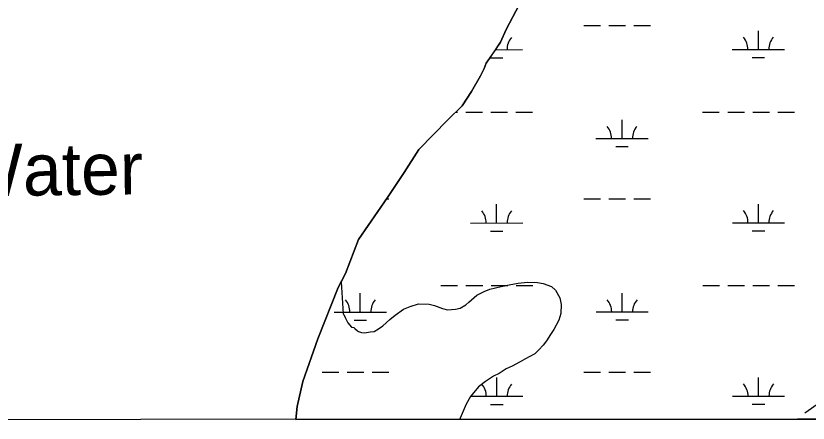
# Model space of a CAD drawing. Extents: x 3279314 to 3317160, y 734079 to 759431.
# Drawn here: x 3297071 to 3298590, y 739456 to 740238 of the extents above; entities that cross this region are included whole.
import ezdxf

# ---------------------------------------------------------------- set-up
doc = ezdxf.new("R2010")
doc.units = 0
for name, color, linetype in [('V-GRID-FRAM', 7, 'Continuous'), ('V-RIVR-IDEN', 7, 'Continuous'), ('V-ROAD-CNTR', 7, 'Continuous'), ('V-SITE-VEGE', 7, 'Continuous'), ('V-TOPO-SHOR', 7, 'Continuous'), ('V-WETL-SWMP', 7, 'Continuous')]:
    doc.layers.add(name, color=color, linetype=linetype)

msp = doc.modelspace()

# ---------------------------------------------------------------- linework, layer by layer
at = {"layer": 'V-GRID-FRAM'}
msp.add_lwpolyline([(3283455.7, 757641.4), (3314923.7, 757657.4), (3314940.9, 739471.9), (3283457, 739455.9), (3283455.7, 757641.4)], dxfattribs=at)
at = {"layer": 'V-ROAD-CNTR'}
msp.add_lwpolyline([(3298583.5, 739475.9), (3298613.5, 739496.6), (3298666.5, 739531.7)], dxfattribs=at)
at = {"layer": 'V-SITE-VEGE'}
for p, q in [((3298035.6, 740258.6), (3298011, 740211.1)), ((3298011, 740211.1), (3298000.3, 740187.3)), ((3298000.3, 740187.3), (3297972.4, 740146.6)), ((3297972.4, 740146.6), (3297968.8, 740136.4)), ((3297968.8, 740136.4), (3297961.7, 740122.8)), ((3297961.7, 740122.8), (3297944.2, 740092.3)), ((3297944.2, 740092.3), (3297926.7, 740065.2)), ((3297926.7, 740065.2), (3297898.9, 740038.2)), ((3297898.9, 740038.2), (3297843.3, 739980.9)), ((3297843.3, 739980.9), (3297815.2, 739936.8)), ((3297815.2, 739936.8), (3297783.7, 739889.3)), ((3297783.7, 739889.3), (3297727.8, 739808.1)), ((3297727.8, 739808.1), (3297702.9, 739743.4)), ((3297702.9, 739743.4), (3297694.4, 739727.1)), ((3297694.4, 739727.1), (3297698.2, 739666)), ((3297979.8, 739713), (3298001.4, 739718.2)), ((3298001.4, 739718.2), (3298016.6, 739721.2)), ((3298016.6, 739721.2), (3298034.2, 739724.9)), ((3298034.2, 739724.9), (3298051.7, 739726.3)), ((3298051.7, 739726.3), (3298070.9, 739726)), ((3298070.9, 739726), (3298082, 739724.2)), ((3298082, 739724.2), (3298097.9, 739718.4)), ((3298097.9, 739718.4), (3298105.8, 739711.1)), ((3297939.5, 739688), (3297954.8, 739701.4)), ((3297954.8, 739701.4), (3297968.5, 739708.3)), ((3297968.5, 739708.3), (3297979.8, 739713)), ((3298105.8, 739711.1), (3298113.5, 739696.6)), ((3297826.9, 739680.1), (3297842.9, 739684.7)), ((3297842.9, 739684.7), (3297863.6, 739684.3)), ((3297863.6, 739684.3), (3297873.2, 739681.8)), ((3297922.6, 739676.3), (3297933.8, 739683.3)), ((3297933.8, 739683.3), (3297939.5, 739688)), ((3298113.5, 739696.6), (3298116.5, 739683.8)), ((3298116.5, 739683.8), (3298115.5, 739666.3)), ((3297797.9, 739663), (3297814, 739674.7)), ((3297814, 739674.7), (3297826.9, 739680.1)), ((3297873.2, 739681.8), (3297889.1, 739676)), ((3297889.1, 739676), (3297898.6, 739673.5)), ((3297898.6, 739673.5), (3297913.8, 739674.8)), ((3297913.8, 739674.8), (3297922.6, 739676.3)), ((3297698.2, 739666), (3297699.8, 739664.4)), ((3297699.8, 739664.4), (3297702.1, 739658.8)), ((3297702.1, 739658.8), (3297707.5, 739648.4)), ((3297774.5, 739642.6), (3297788.2, 739655.1)), ((3297788.2, 739655.1), (3297797.9, 739663)), ((3298112.1, 739653.6), (3298102.3, 739635.4)), ((3298115.5, 739666.3), (3298112.1, 739653.6)), ((3297707.5, 739648.4), (3297714.6, 739640.3)), ((3297714.6, 739640.3), (3297718.6, 739639.4)), ((3297718.6, 739639.4), (3297721, 739637.8)), ((3297721, 739637.8), (3297725.7, 739632.9)), ((3297757.6, 739631.7), (3297766.4, 739637.1)), ((3297766.4, 739637.1), (3297774.5, 739642.6)), ((3297725.7, 739632.9), (3297728.1, 739632.1)), ((3297728.1, 739632.1), (3297733.6, 739629.6)), ((3297733.6, 739629.6), (3297740, 739629.5)), ((3297740, 739629.5), (3297750.4, 739631)), ((3297750.4, 739631), (3297757.6, 739631.7)), ((3298095.7, 739625.9), (3298088.4, 739614)), ((3298102.3, 739635.4), (3298095.7, 739625.9)), ((3298088.4, 739614), (3298081.9, 739605.3)), ((3298073.8, 739596.7), (3298065.7, 739588.8)), ((3298081.9, 739605.3), (3298073.8, 739596.7)), ((3298046.4, 739578.7), (3298037.5, 739573.3)), ((3298065.7, 739588.8), (3298046.4, 739578.7)), ((3298022.3, 739565.5), (3298011, 739560.1)), ((3298037.5, 739573.3), (3298022.3, 739565.5)), ((3297986.9, 739546.1), (3297971.6, 739536)), ((3297997.3, 739551.5), (3297986.9, 739546.1)), ((3298011, 739560.1), (3297997.3, 739551.5)), ((3297971.6, 739536), (3297957.9, 739525.8)), ((3297957.9, 739525.8), (3297942.4, 739506.9)), ((3297942.4, 739506.9), (3297934.2, 739492.6)), ((3297934.2, 739492.6), (3297922.7, 739465.7)), ((3297922.7, 739465.7), (3297922.1, 739463.3)), ((3297922.1, 739463.3), (3300912.9, 739464.8))]:
    msp.add_line(p, q, dxfattribs=at)
at = {"layer": 'V-TOPO-SHOR'}
msp.add_lwpolyline([(3297607.8, 739463.1), (3297610.1, 739488.1), (3297621, 739535.9), (3297649.6, 739617.6), (3297688.8, 739716.2), (3297702.9, 739743.4), (3297727.8, 739808.1), (3297783.7, 739889.3), (3297815.2, 739936.8), (3297843.3, 739980.9), (3297898.9, 740038.2), (3297926.7, 740065.2), (3297944.2, 740092.3), (3297961.7, 740122.8), (3297968.8, 740136.4), (3297972.4, 740146.6), (3297986.4, 740166.9), (3298000.3, 740187.3), (3298011, 740211.1), (3298035.6, 740258.6)], dxfattribs=at)
at = {"layer": 'V-WETL-SWMP'}
for p, q in [((3298035.6, 740258.6), (3298011, 740211.1)), ((3298035.6, 740258.6), (3298011, 740211.1)), ((3298159.6, 740219.3), (3298191.6, 740219.3)), ((3298207.6, 740219.3), (3298239.6, 740219.3)), ((3298255.6, 740219.3), (3298287.6, 740219.3)), ((3298011, 740211.1), (3298000.3, 740187.3)), ((3298011, 740211.1), (3298000.3, 740187.3)), ((3298494.4, 740173), (3298494.4, 740209)), ((3298000.3, 740187.3), (3297972.4, 740146.6)), ((3298000.3, 740187.3), (3297972.4, 740146.6)), ((3297990.4, 740172.7), (3298042.5, 740172.8)), ((3297992.5, 740172.7), (3297992.5, 740175.9)), ((3298444.4, 740173), (3298544.4, 740173)), ((3297980.5, 740157.3), (3298004.5, 740157.3)), ((3298482.4, 740157.6), (3298506.4, 740157.6)), ((3297972.4, 740146.6), (3297968.8, 740136.4)), ((3297972.4, 740146.6), (3297968.8, 740136.4)), ((3297968.8, 740136.4), (3297961.7, 740122.8)), ((3297968.8, 740136.4), (3297961.7, 740122.8)), ((3297961.7, 740122.8), (3297944.2, 740092.3)), ((3297961.7, 740122.8), (3297944.2, 740092.3)), ((3297944.2, 740092.3), (3297926.7, 740065.2)), ((3297944.2, 740092.3), (3297926.7, 740065.2)), ((3297926.7, 740065.2), (3297898.9, 740038.2)), ((3297926.7, 740065.2), (3297898.9, 740038.2)), ((3297913.7, 740052.6), (3297917.7, 740052.6)), ((3297933.7, 740052.6), (3297965.7, 740052.7)), ((3297981.7, 740052.7), (3298013.7, 740052.7)), ((3298029.7, 740052.7), (3298061.7, 740052.7)), ((3298387.6, 740052.9), (3298419.6, 740052.9)), ((3298435.6, 740052.9), (3298467.6, 740052.9)), ((3298483.6, 740052.9), (3298515.6, 740052.9)), ((3298531.6, 740052.9), (3298563.6, 740053)), ((3297898.9, 740038.2), (3297843.3, 739980.9)), ((3297898.9, 740038.2), (3297843.3, 739980.9)), ((3298233.1, 740002), (3298233.1, 740038)), ((3298183.1, 740002), (3298283.1, 740002.1)), ((3298221.1, 739986.6), (3298245.1, 739986.6)), ((3297843.3, 739980.9), (3297815.2, 739936.8)), ((3297843.3, 739980.9), (3297815.2, 739936.8)), ((3297815.2, 739936.8), (3297783.7, 739889.4)), ((3297815.2, 739936.8), (3297783.7, 739889.4)), ((3297783.7, 739889.4), (3297727.8, 739808.1)), ((3297783.7, 739889.4), (3297727.8, 739808.1)), ((3297781.7, 739886.4), (3297785.8, 739886.4)), ((3298159.7, 739886.6), (3298191.7, 739886.6)), ((3298207.7, 739886.6), (3298239.7, 739886.6)), ((3298255.7, 739886.6), (3298287.7, 739886.6)), ((3297992.7, 739840.1), (3297992.7, 739876.1)), ((3298494.6, 739840.3), (3298494.6, 739876.3)), ((3297942.7, 739840), (3298042.7, 739840.1)), ((3298444.6, 739840.3), (3298544.6, 739840.3)), ((3297980.7, 739824.6), (3298004.7, 739824.6)), ((3298482.6, 739824.9), (3298506.6, 739824.9)), ((3297727.8, 739808.1), (3297702.8, 739743.4)), ((3297727.8, 739808.1), (3297702.8, 739743.4)), ((3297702.8, 739743.4), (3297688.8, 739716.2)), ((3297702.8, 739743.4), (3297688.8, 739716.2)), ((3297688.8, 739716.2), (3297649.6, 739617.6)), ((3297688.8, 739716.2), (3297649.6, 739617.6)), ((3297885.9, 739719.9), (3297917.9, 739720)), ((3297933.9, 739720), (3297965.9, 739720)), ((3297981.9, 739720), (3298013.9, 739720)), ((3298029.9, 739720), (3298061.9, 739720)), ((3298387.8, 739720.2), (3298419.8, 739720.2)), ((3298435.8, 739720.2), (3298467.8, 739720.2)), ((3298483.8, 739720.2), (3298515.8, 739720.3)), ((3298531.8, 739720.3), (3298563.8, 739720.3)), ((3297731.3, 739669.1), (3297731.3, 739705.1)), ((3298233.2, 739669.4), (3298233.2, 739705.4)), ((3297681.3, 739669.1), (3297781.3, 739669.1)), ((3298183.2, 739669.4), (3298283.2, 739669.4)), ((3297719.3, 739653.7), (3297743.3, 739653.7)), ((3298221.2, 739653.9), (3298245.2, 739654)), ((3297649.6, 739617.6), (3297621, 739535.9)), ((3297649.6, 739617.6), (3297621, 739535.9)), ((3297658, 739553.7), (3297690, 739553.7)), ((3297706, 739553.7), (3297738, 739553.7)), ((3297754, 739553.7), (3297786, 739553.7)), ((3298159.9, 739553.9), (3298191.9, 739553.9)), ((3298207.9, 739553.9), (3298239.9, 739553.9)), ((3298255.9, 739554), (3298287.9, 739554)), ((3297621, 739535.9), (3297610.1, 739488.1)), ((3297621, 739535.9), (3297610.1, 739488.1)), ((3297992.8, 739507.4), (3297992.8, 739543.4)), ((3298494.8, 739507.6), (3298494.7, 739543.6)), ((3297942.8, 739507.4), (3298042.8, 739507.4)), ((3298444.8, 739507.6), (3298544.8, 739507.7)), ((3297610.1, 739488.1), (3297607.8, 739463.1)), ((3297610.1, 739488.1), (3297607.8, 739463.1)), ((3297980.9, 739492), (3298004.9, 739492)), ((3298482.8, 739492.2), (3298506.8, 739492.2)), ((3297607.8, 739463.1), (3301398.9, 739465)), ((3297607.8, 739463.1), (3301398.9, 739465))]:
    msp.add_line(p, q, dxfattribs=at)
for centre, start, end in [((3298047.8, 740173.2), 139.2573, 180.801), ((3298439.2, 740173.4), 359.2573, 40.801), ((3298549.7, 740173.5), 139.2573, 180.801), ((3298177.8, 740002.5), 359.2573, 40.801), ((3298288.3, 740002.6), 139.2573, 180.801), ((3297937.4, 739840.5), 359.2573, 40.801), ((3298047.9, 739840.6), 139.2573, 180.801), ((3298439.3, 739840.8), 359.2573, 40.801), ((3298549.8, 739840.8), 139.2573, 180.801), ((3297676.1, 739669.6), 359.2573, 40.801), ((3297786.6, 739669.6), 139.2573, 180.801), ((3298178, 739669.8), 359.2573, 40.801), ((3298288.5, 739669.9), 139.2573, 180.801), ((3297937.6, 739507.8), 359.2573, 40.801), ((3298048.1, 739507.9), 139.2573, 180.801), ((3298439.5, 739508.1), 359.2573, 40.801), ((3298550, 739508.1), 139.2573, 180.801)]:
    msp.add_arc(centre, 35.2, start, end, dxfattribs=at)

# ---------------------------------------------------------------- texts
at = {"layer": 'V-RIVR-IDEN'}
msp.add_text('Water', height=100, rotation=0.6586, dxfattribs=at).set_placement((3296958.6, 739891))

doc.saveas('drawing.dxf')
